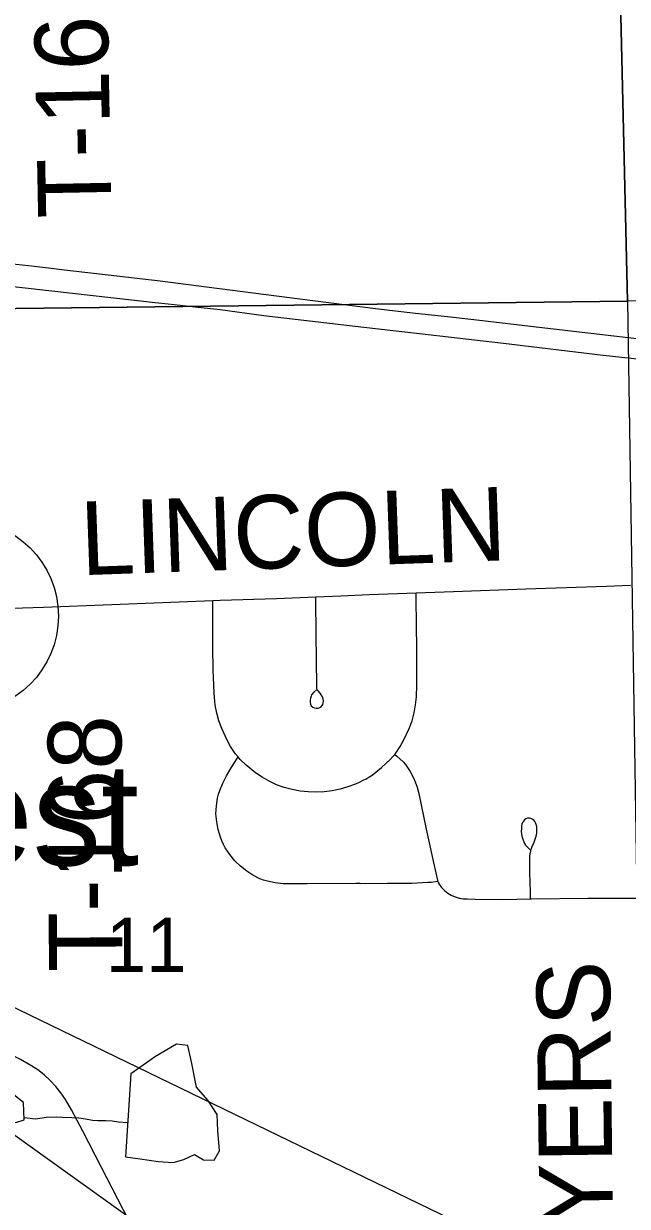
# Model space of a CAD drawing. Extents: x 0 to 34, y 0 to 22.
# Drawn here: x 21.816 to 22.282, y 12.923 to 13.837 of the extents above; entities that cross this region are included whole.
import ezdxf

# ---------------------------------------------------------------- set-up
doc = ezdxf.new("R2010")
doc.units = 0
for name, color, linetype in [('GM_X_County_Road', 7, 'Continuous'), ('GM_X_County_Road_Text', 7, 'Continuous'), ('GM_X_Minor_Lake', 7, 'Continuous'), ('GM_X_Minor_River', 7, 'Continuous'), ('GM_X_Section', 7, 'Continuous'), ('GM_X_Section_Text', 7, 'Continuous'), ('GM_X_Township_Road', 7, 'Continuous'), ('GM_X_Township_Road_Text', 7, 'Continuous'), ('GM_X_Unincorporated', 7, 'Continuous'), ('GM_X_Unincorporated_Text', 7, 'Continuous'), ('GM_X_US_Route', 7, 'Continuous'), ('SH_Text', 7, 'Continuous')]:
    doc.layers.add(name, color=color, linetype=linetype)

msp = doc.modelspace()

# ---------------------------------------------------------------- linework, layer by layer
at = {"layer": 'GM_X_County_Road'}
for points in [[(22.04137, 13.39376), (22.06076, 13.39456), (22.08252, 13.39555), (22.11895, 13.39687)], [(22.11895, 13.39687), (22.14782, 13.39791), (22.2038, 13.39993), (22.26598, 13.40204), (22.28465, 13.40274)], [(21.79029, 13.38462), (21.83076, 13.3859), (21.88365, 13.38775), (21.96172, 13.39092)], [(21.96172, 13.39092), (21.96748, 13.39115), (22.011, 13.39249), (22.04137, 13.39376)], [(22.04844, 12.61763), (22.03341, 12.64683), (22.01368, 12.68556), (21.99633, 12.71856), (21.98514, 12.74073), (21.96798, 12.77383), (21.92424, 12.85943), (21.90978, 12.88706), (21.87555, 12.95333), (21.8613, 12.98093), (21.85261, 12.99748), (21.84779, 13.00553), (21.84423, 13.01068), (21.84035, 13.01562), (21.83608, 13.0202), (21.83145, 13.02446), (21.82646, 13.0283), (21.82121, 13.03174), (21.81306, 13.03636), (21.80207, 13.04191), (21.7933, 13.04589)]]:
    msp.add_lwpolyline(points, dxfattribs=at)
at = {"layer": 'GM_X_Minor_Lake'}
for points in [[(21.8942, 12.96115), (21.90557, 12.95972), (21.9196, 12.95755), (21.93097, 12.95687), (21.93928, 12.95921), (21.94759, 12.96307), (21.95444, 12.95895), (21.96277, 12.95863), (21.96688, 12.96587), (21.96564, 12.98141), (21.96518, 12.99392), (21.95791, 13.00486), (21.94912, 13.01504), (21.94559, 13.03321), (21.94246, 13.04722), (21.93375, 13.04829), (21.91753, 13.03869), (21.89831, 13.02527)], [(21.72131, 12.9898), (21.73835, 12.98994), (21.75085, 12.98889), (21.75844, 12.98705), (21.76604, 12.98256), (21.77776, 12.9853), (21.78417, 12.99104), (21.79515, 12.99112), (21.80956, 12.98782), (21.81599, 12.98976), (21.81552, 13.00303), (21.80676, 13.01017), (21.79953, 13.01505), (21.78665, 13.01495), (21.7749, 13.01676), (21.76651, 13.02466), (21.75819, 13.02346), (21.74834, 13.023), (21.73849, 13.02407), (21.72714, 13.02246), (21.71845, 13.01898), (21.70752, 13.01208)], [(21.89831, 13.02527), (21.8942, 12.96115)]]:
    msp.add_lwpolyline(points, dxfattribs=at)
at = {"layer": 'GM_X_Minor_River'}
msp.add_lwpolyline([(21.81593, 12.99144), (21.82499, 12.99045), (21.83296, 12.9917), (21.84094, 12.99218), (21.84513, 12.99186), (21.85274, 12.99158), (21.85806, 12.99127), (21.8634, 12.99058), (21.86874, 12.98952), (21.87292, 12.98919), (21.87901, 12.98927), (21.88396, 12.98896), (21.88891, 12.98826), (21.8959, 12.98775)], dxfattribs=at)
at = {"layer": 'GM_X_Section'}
for points in [[(22.2584, 14.6473), (23.25514, 14.66297), (23.27399, 13.64315), (22.28222, 13.62221)], [(21.26959, 14.63583), (22.2584, 14.6473), (22.28222, 13.62221), (21.2938, 13.61037)], [(22.28222, 13.62221), (22.29793, 12.62057), (21.31252, 12.61292), (21.2938, 13.61037)]]:
    msp.add_lwpolyline(points, close=True, dxfattribs=at)
at = {"layer": 'GM_X_Township_Road'}
for points in [[(22.10233, 13.27204), (22.10316, 13.27308), (22.10662, 13.27829), (22.10964, 13.2837), (22.11359, 13.29217), (22.11574, 13.29809), (22.11732, 13.30416), (22.11845, 13.31033), (22.11912, 13.31656), (22.11948, 13.32592), (22.11955, 13.34142), (22.11935, 13.35375), (22.11927, 13.37227), (22.11901, 13.39236), (22.11895, 13.39687)], [(22.07989, 13.25302), (22.07772, 13.25182), (22.07496, 13.25029), (22.07209, 13.24899), (22.0662, 13.24688), (22.06016, 13.24525), (22.05405, 13.24401), (22.04785, 13.24319), (22.04161, 13.24289), (22.03536, 13.24306), (22.02916, 13.24378), (22.02301, 13.24489), (22.01696, 13.24647), (22.01106, 13.24862), (22.00542, 13.25131), (21.99999, 13.2544), (21.99482, 13.25793), (21.98746, 13.26365), (21.98293, 13.26801), (21.98122, 13.27007), (21.97893, 13.27284), (21.97548, 13.27804), (21.97245, 13.2835), (21.96864, 13.29203), (21.96647, 13.29787), (21.96474, 13.30388), (21.96361, 13.31001), (21.96268, 13.31927), (21.96221, 13.33137), (21.9621, 13.33714), (21.9618, 13.35498), (21.96174, 13.37968), (21.96172, 13.38688), (21.96172, 13.39092)], [(22.04204, 13.32221), (22.03987, 13.32017), (22.03813, 13.31801), (22.03767, 13.31699), (22.03716, 13.31555), (22.03699, 13.3139), (22.03695, 13.31216), (22.03728, 13.31093), (22.03788, 13.30957), (22.03902, 13.30855), (22.04021, 13.30792), (22.04169, 13.30771), (22.04309, 13.30775), (22.04453, 13.30818), (22.04547, 13.30885), (22.04622, 13.30974), (22.04673, 13.31072), (22.04712, 13.31177), (22.04729, 13.31284), (22.04724, 13.31372), (22.04703, 13.3147), (22.04665, 13.31597), (22.04614, 13.31707), (22.04555, 13.31805), (22.04466, 13.31932), (22.04322, 13.32106), (22.04246, 13.32199), (22.04216, 13.32301), (22.04208, 13.32712), (22.04179, 13.34267), (22.04155, 13.36739), (22.0414, 13.38888), (22.04137, 13.39376)], [(22.07564, 13.17221), (22.07221, 13.17226), (22.03474, 13.172), (22.01606, 13.17219), (22.00994, 13.1728), (22.00395, 13.17406), (22.00102, 13.17495), (21.99816, 13.17603), (21.99267, 13.17874), (21.98792, 13.18178), (21.98306, 13.18562), (21.97869, 13.18992), (21.97481, 13.1947), (21.97139, 13.19978), (21.96994, 13.20247), (21.96868, 13.20526), (21.9676, 13.20812), (21.96594, 13.21403), (21.96481, 13.22007), (21.9642, 13.22618), (21.96428, 13.22919), (21.96457, 13.23226), (21.96548, 13.23834), (21.96617, 13.24131), (21.96707, 13.24423), (21.96939, 13.24991), (21.97222, 13.2554), (21.9759, 13.2616), (21.97867, 13.266), (21.98122, 13.27007)], [(22.07989, 13.25302), (22.08239, 13.25443), (22.08485, 13.25612), (22.09212, 13.26198), (22.09905, 13.26828), (22.1012, 13.2706), (22.10233, 13.27204)], [(22.10233, 13.27204), (22.10389, 13.27074), (22.10642, 13.26864), (22.10884, 13.26631), (22.11069, 13.26413), (22.11428, 13.25878), (22.1171, 13.25333), (22.11935, 13.24764), (22.12104, 13.24174), (22.12677, 13.2144), (22.13133, 13.19313), (22.13331, 13.18403), (22.13534, 13.17488), (22.1356, 13.17408)], [(22.20731, 13.16036), (22.2072, 13.1656), (22.20687, 13.18107), (22.20673, 13.18727), (22.20677, 13.19307), (22.20711, 13.19545), (22.20751, 13.19737), (22.20813, 13.19929), (22.20868, 13.20081), (22.2101, 13.2042), (22.21152, 13.20822), (22.21197, 13.21002), (22.21214, 13.21155), (22.21231, 13.21319), (22.21225, 13.21466), (22.21209, 13.21629), (22.21163, 13.21799), (22.21113, 13.21923), (22.21051, 13.22031), (22.20977, 13.22121), (22.20864, 13.22212), (22.20763, 13.22262), (22.20644, 13.22291), (22.20508, 13.22279), (22.20367, 13.22223), (22.20265, 13.22144), (22.2018, 13.22036), (22.20113, 13.21935), (22.20067, 13.21816), (22.20039, 13.21658), (22.20022, 13.21494), (22.20011, 13.21257), (22.20027, 13.21059), (22.20062, 13.20878), (22.20163, 13.2059), (22.2027, 13.2033), (22.20355, 13.202), (22.20474, 13.20053), (22.20722, 13.19816)], [(22.07564, 13.17221), (22.09679, 13.17249), (22.11546, 13.17269), (22.12785, 13.17323), (22.13043, 13.17344), (22.13374, 13.17384), (22.1356, 13.17408)], [(22.1356, 13.17408), (22.13588, 13.17321), (22.13657, 13.17182), (22.13841, 13.16911), (22.14071, 13.16679), (22.14329, 13.16486), (22.14607, 13.16323), (22.14904, 13.16197), (22.15216, 13.16112), (22.15529, 13.1606), (22.15821, 13.16037), (22.16443, 13.16016), (22.18619, 13.16008), (22.20731, 13.16036)], [(22.20731, 13.16036), (22.20797, 13.16038), (22.25148, 13.16097), (22.27984, 13.16102), (22.28586, 13.16098), (22.28978, 13.16096)]]:
    msp.add_lwpolyline(points, dxfattribs=at)
at = {"layer": 'GM_X_Unincorporated'}
msp.add_circle((21.76796, 13.37892), 0.0744, dxfattribs=at)
at = {"layer": 'GM_X_US_Route'}
for points in [[(21.80454, 13.65135), (21.81926, 13.64984), (21.83467, 13.64789), (21.84701, 13.64646), (21.88095, 13.64242), (21.92109, 13.63794), (21.94881, 13.63439), (22.02893, 13.62399), (22.0875, 13.61654), (22.11837, 13.61289), (22.14308, 13.61031), (22.16777, 13.60753), (22.21406, 13.60219), (22.30045, 13.59197)], [(21.43867, 13.58586), (21.45572, 13.59484), (21.47967, 13.60623), (21.5071, 13.61577), (21.57569, 13.62992), (21.65471, 13.63885), (21.73149, 13.64107), (21.77623, 13.63673), (21.78541, 13.63584), (21.80082, 13.63434), (21.91706, 13.62115), (21.92722, 13.62007), (21.95501, 13.61697), (21.96737, 13.61564), (22.00127, 13.61124), (22.07842, 13.60221), (22.12162, 13.5971), (22.18646, 13.58973), (22.26357, 13.58045), (22.3068, 13.57579)]]:
    msp.add_lwpolyline(points, dxfattribs=at)
at = {"layer": 'SH_Text'}
msp.add_lwpolyline([(22.85646, 12.56861), (21.38517, 13.28132), (22.85646, 12.22703)], close=True, dxfattribs=at)

# ---------------------------------------------------------------- texts
at = {"layer": 'GM_X_County_Road_Text'}
msp.add_text('LINCOLN', height=0.056818, rotation=2.02318, dxfattribs=at).set_placement((21.86017, 13.41046))
at = {"layer": 'GM_X_Section_Text'}
msp.add_text('11', height=0.041856, rotation=0.00001, dxfattribs=at).set_placement((21.87914, 13.104))
at = {"layer": 'GM_X_Township_Road_Text'}
for s, rotation, p in [('T-168', 91.12418, (21.88356, 13.68696)), ('T-168', 90.27987, (21.89192, 13.10402)), ('S GEYERS', 90.72923, (22.27345, 12.7245))]:
    msp.add_text(s, height=0.056818, rotation=rotation, dxfattribs=at).set_placement(p)
at = {"layer": 'GM_X_Unincorporated_Text'}
msp.add_text('Hillcrest', height=0.078977, rotation=0.00001, dxfattribs=at).set_placement((21.52914, 13.1864))

doc.saveas('drawing.dxf')
